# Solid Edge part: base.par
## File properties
Title: Base
Author: Deepak Maini
Template: Normal.par
Last saved by: CADCIM
Revision: 17
Application: Solid Edge
Material: aluminum
Accuracy: 0.99
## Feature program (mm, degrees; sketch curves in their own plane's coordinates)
sketch for "unnamed Protrusion 1" plane through (0, 0, 0) normal (0, 0, 1) x-axis (1, 0, 0)
  line (-85, 25) -> (-85, -25)
  arc centre (-80, -25) radius 5 from (-85, -25) to (-80, -30) ccw
  line (-80, -30) -> (80, -30)
  arc centre (80, -25) radius 5 from (85, -25) to (80, -30) cw
  line (85, -25) -> (85, 25)
  arc centre (80, 25) radius 5 from (80, 30) to (85, 25) cw
  line (80, 30) -> (-80, 30)
  arc centre (-80, 25) radius 5 from (-85, 25) to (-80, 30) cw
extrude "unnamed Protrusion 1" add finite 20 along +normal
sketch for "ExtrudedProtrusion_2" plane through (5, -12, 10) normal (0, -1, 0) x-axis (1, 0, 0)
  line (-50, 10) -> (-50, 50)
  arc centre (15, 50) radius 65 from (-50, 50) to (-20, 104.7723) cw
  line (-20, 104.7723) -> (-20, 144.4119)
  arc centre (-17, 144.4119) radius 3 from (-20, 144.4119) to (-17, 147.4119) cw
  line (-17, 147.4119) -> (37, 147.4119)
  arc centre (37, 144.4119) radius 3 from (37, 147.4119) to (40, 144.4119) cw
  line (40, 144.4119) -> (40, 75.4119)
  line (40, 75.4119) -> (-12.5101, 75.4119)
  line (-12.5101, 35) -> (-12.5101, 75.4119)
  line (9.4899, 10) -> (-12.5101, 35)
  line (32, 35) -> (9.4899, 10)
  line (40, 35) -> (32, 35)
  line (40, 35) -> (40, 10)
extrude "ExtrudedProtrusion_2" add  Plane_Distance = 18 mm
sketch for "unnamed Cutout 1" plane through (5, -12, 88.5) normal (0, -1, 0) x-axis (1, 0, 0)
  line (-20.5101, -68.5) -> (-20.5101, 4.1219)
  arc centre (-25.5101, 4.1219) radius 5 from (-29.3611, 7.3109) to (-20.5101, 4.1219) cw
  arc centre (13, -27.7681) radius 55 from (-42, -27.7681) to (-29.3611, 7.3109) cw
  line (-42, -68.5) -> (-42, -27.7681)
  line (-42, -68.5) -> (-20.5101, -68.5)
extrude "unnamed Cutout 1" cut finite 10 along -normal
sketch for "ExtrudedCutout_2" plane through (5, 0, 0) normal (0, 0, -1) x-axis (1, 0, 0)
  line (-10.5101, 1) -> (-10.5101, -19)
  line (-10.5101, -19) -> (29.4899, -19)
  line (29.4899, -19) -> (29.4899, 1)
  line (29.4899, 1) -> (-10.5101, 1)
  dimension (linear) = 10.5101
extrude "ExtrudedCutout_2" cut finite 147 along -normal
sketch for "ExtrudedProtrusion_3" plane through (25, 9, 157.4119) normal (0, 0, 1) x-axis (1, 0, 0)
  circle centre (-10, 0) radius 15
  dimension (linear) = 10
extrude "ExtrudedProtrusion_3" add finite 18 along +normal
sketch for "Hole_1" plane through (25, 9, 175.4119) normal (0, 0, 1) x-axis (1, 0, 0)
  hole centre (-10, 0) bore radius 10
hole "Hole_1" diameter 20 finite
sketch for "Hole_2" plane through (45, 9, 119.9119) normal (1, 0, 0) x-axis (0, 1, 0)
  hole centre (1, 20.5) bore radius 4
  dimension (linear) = 1
hole "Hole_2" diameter 8 through
mirror "unnamed Mirror 1" of "unnamed Cutout 1" about plane through (5, 9, 88.7059) normal (0, -1, 0)
extrude "unnamed Cutout 2" cut finite 10
fillet "Round_1" radius 3
sketch for "Hole_3" plane through (0, 0, 20) normal (0, 0, 1) x-axis (1, 0, 0)
  hole centre (70, 0) bore radius 6.5
hole "Hole_3" diameter 13 through
sketch for "unnamed Hole 1" plane through (0, 0, 20) normal (0, 0, 1) x-axis (1, 0, 0)
  hole centre (-70, 0) bore radius 6.5
  dimension (linear) = 70
  dimension (linear) = 70
hole "unnamed Hole 1" through
pattern "unnamed Pattern 1" of "Hole_3", "unnamed Hole 1"
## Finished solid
Body 1: solid body, 60 faces, 161 edges, 98 vertices.
  Faces by surface: plane 36, cylinder 23, torus 1
  Edges by curve: line 111, circle 50
Bounding box of the edges (mm; curved faces can reach further): 170.000 x 60.000 x 175.412, from (-85, -30, 0) to (85, 30, 175.4119).
Cylindrical faces by radius (mm): R3 x8, R4 x2, R5 x6, R6.5 x2, R10 x1, R15 x1, R55 x2, R65 x1
Toroidal faces (ring radius, tube radius in mm): R18 r3 x1
Planar faces by outward normal: +x 8, +y 4, +z 5, -x 7, -y 6, -z 4, oblique 2
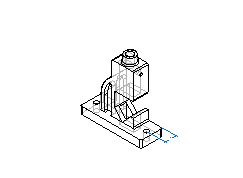
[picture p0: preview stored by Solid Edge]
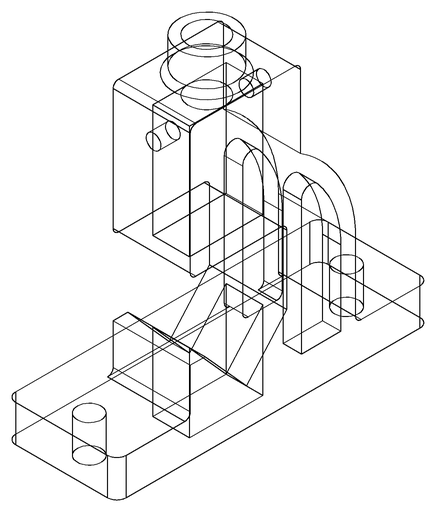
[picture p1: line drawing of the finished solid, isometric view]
